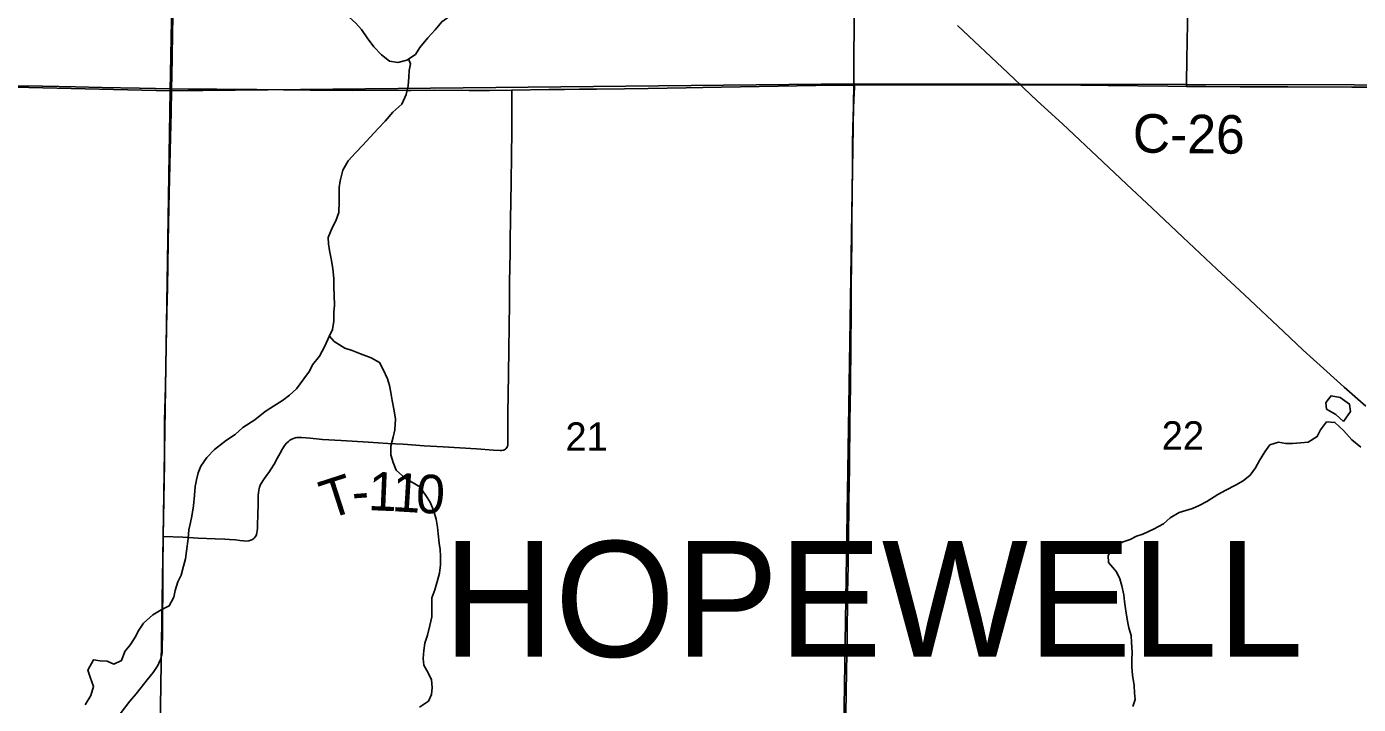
# Model space of a CAD drawing. Extents: x 0 to 34, y 0 to 22.
# Drawn here: x 3.372 to 4.352, y 18.46 to 18.959 of the extents above; entities that cross this region are included whole.
import ezdxf

# ---------------------------------------------------------------- set-up
doc = ezdxf.new("R2010")
doc.units = 0
for name, color, linetype in [('GM_X_County_Road', 7, 'Continuous'), ('GM_X_County_Road_Text', 7, 'Continuous'), ('GM_X_Minor_Lake', 7, 'Continuous'), ('GM_X_Minor_River', 7, 'Continuous'), ('GM_X_Section', 7, 'Continuous'), ('GM_X_Section_Text', 7, 'Continuous'), ('GM_X_State_Route', 7, 'Continuous'), ('GM_X_Township_Road', 7, 'Continuous'), ('GM_X_Township_Road_Text', 7, 'Continuous'), ('GM_X_Township_Text', 7, 'Continuous')]:
    doc.layers.add(name, color=color, linetype=linetype)

msp = doc.modelspace()

# ---------------------------------------------------------------- linework, layer by layer
at = {"layer": 'GM_X_County_Road'}
for points in [[(4.1034, 18.91549), (4.12409, 18.91561), (4.14776, 18.91532), (4.1677, 18.91517), (4.2117, 18.91477), (4.22541, 18.91457)], [(4.22541, 18.91457), (4.23971, 18.91446), (4.26488, 18.91431), (4.30002, 18.9143), (4.3471, 18.91407), (4.37396, 18.91403)]]:
    msp.add_lwpolyline(points, dxfattribs=at)
at = {"layer": 'GM_X_Minor_Lake'}
for points in [[(4.341, 18.66773), (4.34617, 18.67528), (4.34526, 18.6806), (4.33847, 18.68559), (4.33184, 18.68677), (4.32901, 18.68301)], [(4.32901, 18.68301), (4.328, 18.68168), (4.32835, 18.67693), (4.33534, 18.67309), (4.341, 18.66773)]]:
    msp.add_lwpolyline(points, dxfattribs=at)
at = {"layer": 'GM_X_Minor_River'}
for points in [[(3.60071, 18.97095), (3.60916, 18.96556), (3.61408, 18.9612), (3.61843, 18.95646), (3.62259, 18.95021), (3.62732, 18.94376), (3.63318, 18.93769), (3.63886, 18.93315), (3.6451, 18.93201), (3.65172, 18.93391), (3.65796, 18.93808), (3.66117, 18.9432), (3.66722, 18.95041), (3.67252, 18.9561), (3.67743, 18.96217), (3.68868, 18.97016)], [(3.65298, 18.93475), (3.65437, 18.93107), (3.65342, 18.92633), (3.65323, 18.9214), (3.65267, 18.91495), (3.65115, 18.9085), (3.64794, 18.90148), (3.64151, 18.8956), (3.63565, 18.88897), (3.63073, 18.88365), (3.62468, 18.87721), (3.6192, 18.87114), (3.61409, 18.86583), (3.60842, 18.85976), (3.60464, 18.85274), (3.60256, 18.84496), (3.60199, 18.84003), (3.60181, 18.8351), (3.60181, 18.8298), (3.60162, 18.82164), (3.59935, 18.81557), (3.5967, 18.81045), (3.59387, 18.80325), (3.59406, 18.79851), (3.59482, 18.79377), (3.59595, 18.78751), (3.59728, 18.78049), (3.59803, 18.77291), (3.59804, 18.76665), (3.59822, 18.76058), (3.59841, 18.75338), (3.59804, 18.74826), (3.59804, 18.74181), (3.59709, 18.73556), (3.59464, 18.73044), (3.59142, 18.72323), (3.58745, 18.71602), (3.58235, 18.70957), (3.58008, 18.70483), (3.57592, 18.69933), (3.57062, 18.69194), (3.56533, 18.68719), (3.56022, 18.6834), (3.55361, 18.67904), (3.54737, 18.67524), (3.5398, 18.66917), (3.5311, 18.66329), (3.52543, 18.65817), (3.519, 18.65399), (3.51011, 18.64716), (3.50444, 18.64128), (3.50009, 18.63503), (3.4982, 18.6301), (3.49688, 18.62479), (3.49593, 18.61985), (3.49556, 18.6136), (3.49461, 18.60582), (3.49348, 18.59824), (3.49253, 18.5935), (3.49121, 18.588), (3.49083, 18.58174), (3.4897, 18.57226), (3.48894, 18.56676), (3.48743, 18.56126), (3.48554, 18.55463), (3.48327, 18.54969), (3.4812, 18.54344), (3.48025, 18.53851), (3.47685, 18.53206), (3.47098, 18.52921), (3.46474, 18.52542), (3.45794, 18.51935), (3.45453, 18.51423), (3.45189, 18.50911), (3.44848, 18.50361), (3.44432, 18.49849), (3.44168, 18.49185), (3.43619, 18.48919), (3.43128, 18.49147), (3.42617, 18.49165), (3.42106, 18.49241), (3.4169, 18.48463), (3.41861, 18.47951), (3.42126, 18.47269), (3.41918, 18.46605), (3.41502, 18.45922)], [(3.59473, 18.73063), (3.59823, 18.72683), (3.60617, 18.72172), (3.61147, 18.72001), (3.61771, 18.71774), (3.62546, 18.71471), (3.63171, 18.7113), (3.63435, 18.70599), (3.63757, 18.69916), (3.6389, 18.69442), (3.63984, 18.68912), (3.64098, 18.68324), (3.64211, 18.67679), (3.64325, 18.66978), (3.64287, 18.66162), (3.64155, 18.65631), (3.64004, 18.64968), (3.64004, 18.64323), (3.64155, 18.63773), (3.64382, 18.63204), (3.65101, 18.6256), (3.65631, 18.62257), (3.66122, 18.61972), (3.66576, 18.61328), (3.66879, 18.60835), (3.67163, 18.60172), (3.67333, 18.59584), (3.67428, 18.58996), (3.67484, 18.58503), (3.6756, 18.57821), (3.67617, 18.57347), (3.67636, 18.56873), (3.67636, 18.56228), (3.67579, 18.55621), (3.67428, 18.55071), (3.6722, 18.54388), (3.67012, 18.53801), (3.67013, 18.52397), (3.66861, 18.51772), (3.66691, 18.51051), (3.66502, 18.50463), (3.66427, 18.49932), (3.6637, 18.49344), (3.66427, 18.48833), (3.66767, 18.48226), (3.66975, 18.47752), (3.67032, 18.47202), (3.66995, 18.4669), (3.66768, 18.46197), (3.66106, 18.45742)], [(4.34095, 18.66128), (4.33454, 18.66721), (4.32847, 18.66763), (4.32407, 18.66179), (4.32156, 18.65668), (4.31489, 18.65256), (4.30939, 18.65203), (4.30331, 18.65151), (4.29857, 18.65173), (4.29307, 18.65272), (4.2868, 18.65068), (4.28297, 18.64559), (4.27913, 18.63916), (4.27605, 18.63368), (4.27222, 18.6284), (4.26706, 18.62426), (4.26154, 18.62089), (4.2543, 18.61734), (4.24839, 18.61397), (4.24039, 18.6089), (4.23468, 18.60591), (4.22973, 18.60386), (4.22497, 18.60238), (4.22003, 18.60071), (4.21336, 18.59696), (4.20859, 18.59244), (4.20116, 18.58851), (4.19335, 18.58497), (4.1886, 18.5833), (4.18384, 18.58086), (4.1787, 18.57919), (4.17127, 18.57526), (4.16781, 18.56922), (4.16796, 18.5639), (4.1738, 18.55703), (4.17623, 18.55189), (4.17771, 18.54695), (4.17918, 18.5401), (4.17971, 18.53536), (4.1808, 18.52833), (4.18207, 18.52092), (4.18299, 18.51598), (4.18465, 18.51027), (4.185, 18.50534), (4.18532, 18.49774), (4.18529, 18.49262), (4.18506, 18.48731), (4.18577, 18.48104), (4.18685, 18.47345), (4.1872, 18.46813), (4.18754, 18.46319), (4.18579, 18.45789)], [(4.35357, 18.64885), (4.34697, 18.6544), (4.34095, 18.66128)]]:
    msp.add_lwpolyline(points, dxfattribs=at)
at = {"layer": 'GM_X_Section'}
for points in [[(3.4871, 19.41486), (3.47768, 18.91133), (2.97779, 18.923), (2.98702, 19.42864)], [(3.98263, 19.41835), (3.98059, 18.9165), (3.47768, 18.91133), (3.4871, 19.41486)], [(4.47488, 19.41917), (4.47149, 18.91545), (3.98059, 18.9165), (3.98263, 19.41835)], [(2.97779, 18.923), (3.47768, 18.91133), (3.4698, 18.41139), (2.96987, 18.41871)], [(3.47768, 18.91133), (3.98059, 18.9165), (3.9728, 18.4103), (3.4698, 18.41139)], [(3.98059, 18.9165), (4.47149, 18.91545), (4.46827, 18.41225), (3.9728, 18.4103)]]:
    msp.add_lwpolyline(points, close=True, dxfattribs=at)
at = {"layer": 'GM_X_State_Route'}
for points in [[(4.05678, 18.9593), (4.09396, 18.92448), (4.1034, 18.91549)], [(4.1034, 18.91549), (4.10565, 18.91335), (4.1156, 18.90401), (4.13408, 18.88688), (4.16373, 18.85896), (4.18124, 18.84267), (4.2002, 18.82483), (4.22274, 18.80358), (4.24775, 18.78002), (4.26799, 18.76099), (4.29669, 18.73403), (4.31126, 18.7203), (4.31872, 18.71347), (4.32853, 18.70468), (4.3414, 18.69304), (4.35732, 18.67903)]]:
    msp.add_lwpolyline(points, dxfattribs=at)
at = {"layer": 'GM_X_Township_Road'}
for points in [[(4.22541, 18.91457), (4.22545, 18.91732), (4.22569, 18.93441), (4.22647, 18.97418), (4.22708, 19.01583), (4.22745, 19.03634), (4.22769, 19.05249), (4.22782, 19.06087), (4.22791, 19.0674), (4.22811, 19.07827), (4.22846, 19.10096), (4.22893, 19.13079), (4.22931, 19.15877), (4.22932, 19.18146), (4.22947, 19.23367), (4.22944, 19.26196), (4.22944, 19.2806), (4.22958, 19.34587), (4.22973, 19.37291), (4.22983, 19.40182), (4.22956, 19.41969)], [(3.47857, 18.91283), (3.47878, 18.92275), (3.4791, 18.93583), (3.47926, 18.95405), (3.47975, 18.97592), (3.48019, 18.99731), (3.48072, 19.01918), (3.48108, 19.04081), (3.48157, 19.06445), (3.48193, 19.08403), (3.48197, 19.09706), (3.48228, 19.11299), (3.48266, 19.12696), (3.48276, 19.14345), (3.48302, 19.15652), (3.48328, 19.16766), (3.48329, 19.16935)], [(2.97847, 18.92365), (2.98457, 18.92355), (2.99979, 18.92323), (3.01782, 18.92283), (3.05294, 18.92212), (3.08024, 18.92147), (3.10516, 18.92094), (3.12148, 18.92066), (3.13155, 18.92044), (3.13901, 18.92024), (3.17537, 18.9194), (3.19649, 18.91898), (3.21732, 18.91849), (3.24683, 18.9177), (3.26983, 18.91721), (3.29065, 18.9167), (3.32548, 18.91595), (3.34258, 18.9155), (3.36557, 18.91506), (3.38357, 18.91473), (3.4078, 18.91415), (3.42737, 18.9138), (3.45504, 18.91329), (3.47857, 18.91283)], [(3.47244, 18.58326), (3.47296, 18.61009), (3.47332, 18.63715), (3.47331, 18.65479), (3.47349, 18.66854), (3.47408, 18.69336), (3.47461, 18.72321), (3.47514, 18.74859), (3.47554, 18.76639), (3.47578, 18.783), (3.47619, 18.7999), (3.47668, 18.8256), (3.47781, 18.87725), (3.47818, 18.89526), (3.47857, 18.91283)], [(3.47857, 18.91283), (3.49078, 18.91258), (3.512, 18.91239), (3.54143, 18.91221), (3.5805, 18.91171), (3.61137, 18.91159), (3.63351, 18.91164), (3.65198, 18.91158)], [(3.72894, 18.91173), (3.75614, 18.91214), (3.76763, 18.91227), (3.77881, 18.9124), (3.79125, 18.91254), (3.81176, 18.91274), (3.82917, 18.91301), (3.85713, 18.91355), (3.86956, 18.9138), (3.91099, 18.91444), (3.95254, 18.9151), (3.97554, 18.91544), (3.98119, 18.91554)], [(3.97477, 18.4518), (3.97508, 18.46888), (3.97551, 18.49747), (3.97564, 18.50741), (3.97607, 18.54159), (3.97637, 18.56179), (3.97666, 18.5795), (3.97704, 18.60975), (3.97733, 18.63326), (3.97777, 18.67154), (3.97783, 18.67738), (3.9781, 18.69665), (3.97831, 18.7215), (3.97858, 18.75009), (3.97871, 18.77216), (3.9788, 18.77961), (3.97904, 18.8051), (3.97917, 18.81566), (3.97956, 18.85681), (3.97971, 18.87315), (3.98022, 18.89303), (3.98093, 18.90969), (3.98108, 18.91321), (3.98119, 18.91554)], [(3.98119, 18.91554), (3.99236, 18.91574), (4.00741, 18.91574), (4.03455, 18.91579), (4.08213, 18.91563), (4.1034, 18.91549)], [(3.47244, 18.58326), (3.48697, 18.58256), (3.49814, 18.58198), (3.51056, 18.58143), (3.5177, 18.58112), (3.52122, 18.58098), (3.52575, 18.58065), (3.52887, 18.58029), (3.53159, 18.57996), (3.53339, 18.57979), (3.53545, 18.57996), (3.53685, 18.58034), (3.53769, 18.58069), (3.53845, 18.58115), (3.53907, 18.58165), (3.53973, 18.5823), (3.5403, 18.58317), (3.54075, 18.58387), (3.54108, 18.58457), (3.54141, 18.58576), (3.54157, 18.58724), (3.54178, 18.58925), (3.54194, 18.5932), (3.54202, 18.5976), (3.54231, 18.60879), (3.54243, 18.61348), (3.54255, 18.61528), (3.54276, 18.61726), (3.543, 18.61837), (3.54333, 18.61952), (3.54407, 18.62141), (3.5449, 18.62281), (3.54579, 18.62417), (3.54855, 18.62807), (3.5502, 18.63025), (3.55188, 18.63289), (3.55402, 18.63634), (3.55653, 18.64103), (3.55842, 18.64453), (3.56027, 18.64773), (3.56183, 18.65028), (3.56319, 18.65189), (3.56458, 18.65316), (3.56569, 18.65399), (3.56717, 18.65493), (3.56836, 18.65542), (3.56951, 18.65571), (3.57083, 18.65596), (3.57223, 18.65604), (3.57412, 18.65596), (3.57753, 18.65572), (3.58058, 18.65547), (3.58963, 18.65469), (3.60332, 18.65375), (3.62338, 18.65252), (3.63765, 18.65166), (3.649, 18.65105), (3.66446, 18.65002), (3.6784, 18.64908), (3.70303, 18.64766), (3.71549, 18.64675), (3.7204, 18.64656), (3.72162, 18.64655), (3.72273, 18.64675), (3.7236, 18.64708), (3.72425, 18.64741), (3.72475, 18.64787), (3.72483, 18.64798), (3.7253, 18.64862), (3.72571, 18.64945), (3.72598, 18.65066), (3.72611, 18.65221), (3.72614, 18.65514), (3.7261, 18.66185), (3.72606, 18.66682), (3.72609, 18.67398), (3.72646, 18.70227), (3.72674, 18.72155), (3.72694, 18.73734), (3.72714, 18.75535), (3.72734, 18.77069), (3.72775, 18.79174), (3.72774, 18.80112), (3.72807, 18.81691), (3.72827, 18.8297), (3.72847, 18.84368), (3.72863, 18.86379), (3.72895, 18.88122), (3.72907, 18.89487), (3.72905, 18.90605), (3.72894, 18.91173)], [(3.65198, 18.91158), (3.65456, 18.91157), (3.67237, 18.91165), (3.69757, 18.9115), (3.71264, 18.9116), (3.72894, 18.91173)], [(3.44078, 18.45272), (3.44789, 18.46181), (3.45245, 18.46736), (3.46054, 18.47755), (3.46495, 18.48295), (3.46606, 18.48451), (3.46705, 18.48603), (3.46845, 18.48828), (3.46931, 18.4899), (3.47001, 18.4915), (3.47042, 18.49265), (3.47103, 18.49451), (3.4714, 18.49599), (3.47161, 18.49771), (3.47169, 18.49907), (3.47177, 18.5008), (3.47177, 18.50244), (3.47181, 18.51021), (3.47193, 18.52888), (3.47213, 18.53867), (3.47221, 18.54706), (3.47225, 18.56001), (3.47244, 18.58326)]]:
    msp.add_lwpolyline(points, dxfattribs=at)

# ---------------------------------------------------------------- texts
at = {"layer": 'GM_X_County_Road_Text'}
msp.add_text('C-26', height=0.028409, rotation=359.31116, dxfattribs=at).set_placement((4.18576, 18.86586))
at = {"layer": 'GM_X_Section_Text'}
for s, p in [('21', (3.76841, 18.64623)), ('22', (4.20716, 18.64707))]:
    msp.add_text(s, height=0.020928, rotation=0.00001, dxfattribs=at).set_placement(p)
at = {"layer": 'GM_X_Township_Road_Text'}
for s, rotation, p in [('T', 17.9308, (3.59364, 18.59557)), ('1', 357.5638, (3.62286, 18.60263)), ('1', 356.51131, (3.64021, 18.6019)), ('0', 356.79219, (3.65783, 18.60082)), ('-', 4.33644, (3.61212, 18.60177))]:
    msp.add_text(s, height=0.02841, rotation=rotation, dxfattribs=at).set_placement(p)
at = {"layer": 'GM_X_Township_Text'}
msp.add_text('HOPEWELL', height=0.085227, rotation=0.00001, dxfattribs=at).set_placement((3.6782, 18.49457))

doc.saveas('drawing.dxf')
